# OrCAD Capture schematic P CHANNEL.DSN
size A
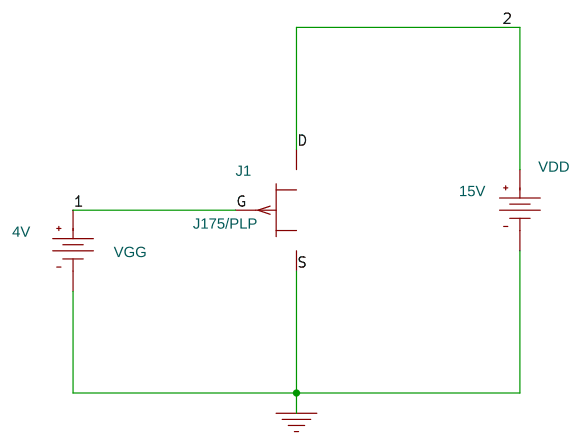
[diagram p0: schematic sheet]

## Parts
J1  J175/PLP  [TO92]
VDD  VDC
VGG  VDC

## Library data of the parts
J1 = J175_PLP
VDD = VDC: DC: 15V
VGG = VDC: DC: 4V

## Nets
0: J1.3(s) VDD.1(-) VGG.1(-)
1: J1.2(g) VGG.0(+)
2: J1.1(d) VDD.0(+)
